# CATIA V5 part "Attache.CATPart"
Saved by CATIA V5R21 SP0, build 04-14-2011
Part number: Attache
Bounding box of the stored display mesh (mm): x -35 to 35, y 0 to 10, z 84 to 96
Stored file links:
  C:\Users\zerma\Pictures\CAO\Attache_test_1.CATPart
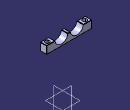
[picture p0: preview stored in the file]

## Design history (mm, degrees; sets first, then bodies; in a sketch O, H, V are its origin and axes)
Body1 (main body)
  DatumCurve1
  DatumCurve2
  Sketch1 on zx-plane, origin (0, 0, 0), H (-1, 0, 0), V (0, 0, 1)
    circle A1 centre (-12, 97) radius 10
    point P1 (-12, 97)
    circle A2 centre (12, 97) radius 10
    point P2 (12, 97)
    line L1 (-35, 110) -> (35, 110)
    point P3 (-35, 110)
    point P4 (35, 110)
    line L2 (-35, 84) -> (35, 84)
    point P5 (-35, 84)
    point P6 (35, 84)
    point P7 (-35, 84)
    point P8 (-35, 110)
    line L3 (35, 110) -> (35, 84)
    line L4 (-35, 110) -> (-35, 84)
    radius A1 = 10
    radius A2 = 10
    distance P1 P2 = 24
    length L1 = 70
    distance P2 L1 = 13
    distance P2 L2 = 13
    horizontal: L1 H, L2 H
    symmetry: P2 P1 V, P6 P7 V, P4 P8 V
    coincidence: P3 P8, P7 P5
    vertical: L3 V, L4 V
  Pad1: profile Sketch1, direction (0, 1, 0), length 10
  Sketch2 on start face of Pad1, origin (0, 0, 0), H (1, 0, 0), V (0, 0, 1)
    line L1 (-35, 110) -> (35, 110)
    line L2 (35, 110) -> (35, 96)
    line L3 (35, 96) -> (-35, 96)
    line L4 (-35, 96) -> (-35, 110)
    reference projected line E1 (-35, 110) -> (35, 110) from edge [start face of Pad1 | face of Pad1 from Sketch1.L1]
    reference projected line E2 (-35, 84) -> (-35, 110) from edge [start face of Pad1 | face of Pad1 from Sketch1.L3]
    reference projected line E3 (35, 110) -> (35, 84) from edge [start face of Pad1 | face of Pad1 from Sketch1.L4]
    length L2 = 14
    horizontal: L1 H, L3 H
    vertical: L2 V, L4 V
    coincidence: L1 E1, L4 E2, L2 E3
  Pocket1: profile Sketch2, direction (0, 1, 0), length 10
  Sketch3 on face of Pad1 from Sketch1.L2, origin (12.8428, 5.2011, 84), H (1, 0, 0), V (0, -1, 0)
    point P1 (16.1572, 0.2011)
    reference projected line E1 (22.1572, 5.2011) -> (22.1572, -4.7989) from edge [face of Pad1 from Sketch1.L2 | face of Pad1 from Sketch1.L4]
    reference projected line E3 (22.1572, 5.2011) -> (-47.8428, 5.2011) from edge [start face of Pad1 | face of Pad1 from Sketch1.L2]
    distance P1 E1 = 6
    distance P1 E3 = 5
  Hole1: placed by Sketch3, at (29, 5, 84) direction (0, 0, 1), diameter 6.3, through (limit type 6)
  Mirror1: of Hole1, about yz-plane
  Chamfer1: length 0.5, angle 45, on edge [face of Pad1 from Sketch1.A1 | face of Pocket1 from Sketch2.L3]; edge [face of Pocket1 from Sketch2.L3 | face of Pad1 from Sketch1.A2]; edge [face of Pad1 from Sketch1.A2 | face of Pocket1 from Sketch2.L3]; edge [face of Pocket1 from Sketch2.L3 | face of Pad1 from Sketch1.A1]; edge [face of Pocket1 from Sketch2.L3 | end face of Pad1] (x3); edge [start face of Pad1 | face of Pocket1 from Sketch2.L3] (x3); edge [face of Pocket1 from Sketch2.L3 | face of Pad1 from Sketch1.L3]; edge [face of Pad1 from Sketch1.L4 | face of Pocket1 from Sketch2.L3]; edge [start face of Pad1 | face of Pad1 from Sketch1.L4]; edge [start face of Pad1 | face of Pad1 from Sketch1.L3]; edge [start face of Pad1 | face of Pad1 from Sketch1.L2]; edge [face of Pad1 from Sketch1.L3 | face of Pad1 from Sketch1.L2]; edge [face of Pad1 from Sketch1.L3 | end face of Pad1]; edge [face of Pad1 from Sketch1.L2 | end face of Pad1]; edge [face of Pad1 from Sketch1.L2 | face of Pad1 from Sketch1.L4]; edge [face of Pad1 from Sketch1.L4 | end face of Pad1]
  CLDGeom1 "Maillage.1"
